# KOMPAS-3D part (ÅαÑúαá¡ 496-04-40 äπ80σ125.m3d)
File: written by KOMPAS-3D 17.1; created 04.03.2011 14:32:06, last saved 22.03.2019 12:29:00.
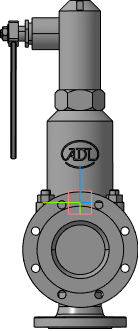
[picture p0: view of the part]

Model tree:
1. Операция без истории:1

Referenced files in C:\Users\tra\Desktop\Детали с марк. для Сферы\bsv\Desktop\Si 57\: VIC_496_80x125_3d.a3d
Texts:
  Viktor2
